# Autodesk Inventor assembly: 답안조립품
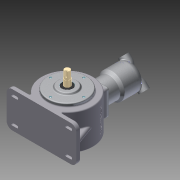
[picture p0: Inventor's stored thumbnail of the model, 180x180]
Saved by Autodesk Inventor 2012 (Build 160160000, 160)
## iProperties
Created: 2015-06
Part Number: 답안조립품
Document SubType Name: Assembly
Designer: user
Author: user
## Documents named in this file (8)
- C:\Users\user\Desktop\450606V1020\답안조립품.iam
- C:\Users\user\Desktop\450606V1020\본체.ipt
- C:\Users\user\Desktop\450606V1020\450606V1020\메인 크랭크 축-구동부.ipt
- C:\Users\user\Desktop\450606V1020\450606V1020\베어링 6204.ipt
- C:\Users\user\Desktop\450606V1020\450606V1020\메인커버.ipt
- C:\Users\user\Desktop\450606V1020\450606V1020\실린더.ipt
- C:\Users\user\Desktop\450606V1020\450606V1020\실린더헤드.ipt
- C:\Users\user\Desktop\450606V1020\450606V1020\오일실.ipt
